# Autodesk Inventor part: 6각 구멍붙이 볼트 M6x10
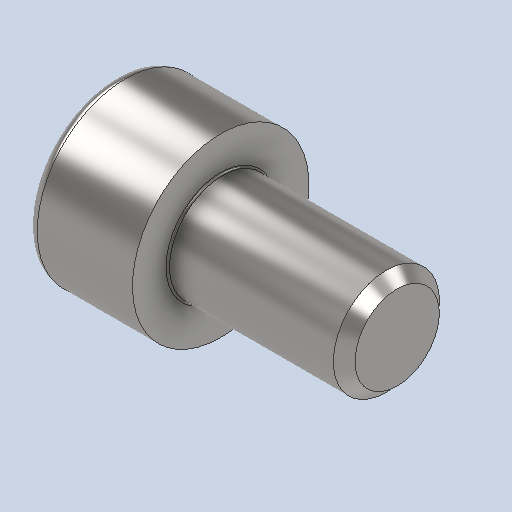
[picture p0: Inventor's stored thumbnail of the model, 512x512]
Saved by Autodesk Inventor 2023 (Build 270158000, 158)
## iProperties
Created: 2026-04
Part Number: 6각 구멍붙이 볼트 M6x10
Material: 강철, 연강
Description: 6각머리 태핑 나사
Document SubType Name: Modeling
Designer: home
Density: 7.85 g/cm^3
Appearance: 기본값
Author: jhkim
Sending System: Autodesk Inventor 2027
Preprocessor: ST-DEVELOPER v20.1
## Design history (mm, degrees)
feature "Solid1"
node "솔리드1"
